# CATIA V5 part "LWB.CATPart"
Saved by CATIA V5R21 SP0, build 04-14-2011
Part number: LWB.SLDPRT
Bounding box of the stored display mesh (mm): x 1.55 to 5.05, y 3.678 to 6.478, z -1.805 to -0.004
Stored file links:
  C:\Users\user\Desktop\CATIA文件\0-最新文件(2025.3月之前的慎用)\LWB\LWB.CATPart
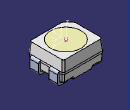
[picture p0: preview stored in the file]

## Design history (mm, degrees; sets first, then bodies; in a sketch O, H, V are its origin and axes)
AxisSystem1: origin (3.2981, 5.075, -0.0046), X (0, -1, 0), Y (1, 0, 0), Z (0, 0, 1)
Set1
  DatumSurface1 to DatumSurface120
  Line1: stored without definition
  Circle1: stored without definition
  Line2: stored without definition
  Circle2: stored without definition
  Line3 to Line38: stored without definition
  Circle3: stored without definition
  Line39: stored without definition
  Circle4: stored without definition
  Line40 to Line43: stored without definition
  Circle5: stored without definition
  Circle6: stored without definition
  Line44 to Line46: stored without definition
  Circle7: stored without definition
  Line47: stored without definition
  Circle8: stored without definition
  Line48 to Line50: stored without definition
  Circle9 to Circle11: stored without definition
  Line51: stored without definition
  Circle12: stored without definition
  Line52: stored without definition
  Circle13 to Circle15: stored without definition
  Line53: stored without definition
  Circle16: stored without definition
  Line54: stored without definition
  Circle17 to Circle19: stored without definition
  Line55: stored without definition
  Circle20: stored without definition
  Line56: stored without definition
  Circle21 to Circle23: stored without definition
  Line57: stored without definition
  Circle24: stored without definition
  Line58: stored without definition
  Circle25: stored without definition
  Circle26: stored without definition
  Line59 to Line62: stored without definition
  Circle27: stored without definition
  Circle28: stored without definition
  Line63 to Line66: stored without definition
  Circle29: stored without definition
  Circle30: stored without definition
  Line67: stored without definition
  Circle31: stored without definition
  Line68: stored without definition
  Circle32: stored without definition
  Line69 to Line72: stored without definition
  Circle33: stored without definition
  Line73: stored without definition
  Circle34: stored without definition
  Circle35: stored without definition
  Line74: stored without definition
  Circle36: stored without definition
  Line75 to Line78: stored without definition
  Circle37: stored without definition
  Line79: stored without definition
  Circle38: stored without definition
  Line80 to Line82: stored without definition
  Circle39: stored without definition
  Line83: stored without definition
  Circle40: stored without definition
  Line84 to Line86: stored without definition
  Circle41: stored without definition
  Line87: stored without definition
  Circle42: stored without definition
  Line88 to Line90: stored without definition
  Circle43: stored without definition
  Line91: stored without definition
  Circle44: stored without definition
  Circle45: stored without definition
  Line92: stored without definition
  Circle46: stored without definition
  Line93 to Line95: stored without definition
  Circle47: stored without definition
  Line96: stored without definition
  Circle48: stored without definition
  Circle49: stored without definition
  Line97: stored without definition
  Circle50: stored without definition
  Line98 to Line100: stored without definition
  Circle51: stored without definition
  Line101: stored without definition
  Circle52: stored without definition
  Line102 to Line104: stored without definition
  Circle53: stored without definition
  Line105: stored without definition
  Circle54: stored without definition
  Line106 to Line108: stored without definition
  Circle55: stored without definition
  Line109: stored without definition
  Circle56: stored without definition
  Line110 to Line112: stored without definition
  Circle57: stored without definition
  Line113: stored without definition
  Circle58: stored without definition
  Line114: stored without definition
  Circle59: stored without definition
  Line115: stored without definition
  Circle60: stored without definition
  Line116 to Line118: stored without definition
  Circle61: stored without definition
  Line119: stored without definition
  Circle62: stored without definition
  Line120 to Line132: stored without definition
  Circle63: stored without definition
  Line133: stored without definition
  Circle64: stored without definition
  Line134 to Line136: stored without definition
  Circle65: stored without definition
  Line137: stored without definition
  Circle66: stored without definition
  Line138: stored without definition
  Circle67: stored without definition
  Line139: stored without definition
  Circle68: stored without definition
  Line140 to Line143: stored without definition
  Circle69: stored without definition
  Circle70: stored without definition
  Line144 to Line153: stored without definition
  Circle71: stored without definition
  Line154: stored without definition
  Circle72: stored without definition
  Line155 to Line157: stored without definition
  Circle73: stored without definition
  Line158: stored without definition
  Circle74: stored without definition
  Line159 to Line161: stored without definition
  Circle75: stored without definition
  Line162: stored without definition
  Circle76: stored without definition
  Line163 to Line165: stored without definition
  Circle77: stored without definition
  Line166: stored without definition
  Circle78: stored without definition
  Line167 to Line169: stored without definition
  Circle79: stored without definition
  Line170: stored without definition
  Circle80: stored without definition
  Line171 to Line173: stored without definition
  Circle81: stored without definition
  Line174: stored without definition
  Circle82: stored without definition
  Line175 to Line177: stored without definition
  Circle83: stored without definition
  Line178: stored without definition
  Circle84: stored without definition
  Line179 to Line181: stored without definition
  Circle85: stored without definition
  Line182: stored without definition
  Circle86: stored without definition
  Line183 to Line185: stored without definition
  Circle87: stored without definition
  Line186: stored without definition
  Circle88: stored without definition
  Line187 to Line189: stored without definition
  Circle89: stored without definition
  Line190: stored without definition
  Circle90: stored without definition
  Line191 to Line193: stored without definition
  Circle91: stored without definition
  Line194: stored without definition
  Circle92: stored without definition
  Line195 to Line197: stored without definition
  Circle93: stored without definition
  Line198: stored without definition
  Circle94: stored without definition
  Line199 to Line201: stored without definition
  Circle95: stored without definition
  Line202: stored without definition
  Circle96: stored without definition
  Line203 to Line205: stored without definition
  Circle97: stored without definition
  Line206: stored without definition
  Circle98: stored without definition
  Line207 to Line209: stored without definition
  Circle99: stored without definition
  Line210: stored without definition
  Circle100: stored without definition
  Line211 to Line213: stored without definition
  Circle101: stored without definition
  Line214: stored without definition
  Circle102: stored without definition
  Line215 to Line217: stored without definition
  Circle103: stored without definition
  Line218: stored without definition
  Circle104: stored without definition
  Line219 to Line221: stored without definition
  Circle105: stored without definition
  Line222: stored without definition
  Circle106: stored without definition
  Line223 to Line225: stored without definition
  Circle107: stored without definition
  Line226: stored without definition
  Circle108: stored without definition
  Line227 to Line229: stored without definition
  Circle109: stored without definition
  Line230: stored without definition
  Circle110: stored without definition
  Line231 to Line241: stored without definition
  DatumSurface121 to DatumSurface179
  Circle111: stored without definition
  Line242: stored without definition
  Circle112: stored without definition
  Line243: stored without definition
  Circle113 to Circle115: stored without definition
  Line244: stored without definition
  Circle116: stored without definition
  Line245 to Line248: stored without definition
  Circle117: stored without definition
  Circle118: stored without definition
  Line249 to Line251: stored without definition
  Circle119: stored without definition
  Line252: stored without definition
  Circle120: stored without definition
  Line253 to Line256: stored without definition
  Circle121: stored without definition
  Circle122: stored without definition
  Line257 to Line261: stored without definition
  Circle123: stored without definition
  Circle124: stored without definition
  Line262 to Line265: stored without definition
  Circle125 to Circle128: stored without definition
  Line266 to Line270: stored without definition
  Circle129: stored without definition
  Circle130: stored without definition
  Line271 to Line274: stored without definition
  Circle131: stored without definition
  Circle132: stored without definition
  Line275 to Line277: stored without definition
  Circle133: stored without definition
  Circle134: stored without definition
  Line278 to Line282: stored without definition
  Circle135: stored without definition
  Circle136: stored without definition
  Line283 to Line286: stored without definition
  Circle137: stored without definition
  Circle138: stored without definition
  Line287 to Line289: stored without definition
  Circle139: stored without definition
  Circle140: stored without definition
  Line290 to Line293: stored without definition
  Circle141: stored without definition
  Circle142: stored without definition
  Line294 to Line298: stored without definition
  Circle143: stored without definition
  Circle144: stored without definition
  Line299 to Line302: stored without definition
  Circle145: stored without definition
  Circle146: stored without definition
  Line303 to Line306: stored without definition
  Circle147: stored without definition
  Circle148: stored without definition
  Line307 to Line310: stored without definition
  Circle149: stored without definition
  Circle150: stored without definition
  Line311: stored without definition
  Circle151: stored without definition
  Line312: stored without definition
  Circle152 to Circle154: stored without definition
  Line313 to Line316: stored without definition
  Circle155: stored without definition
  Circle156: stored without definition
  Line317 to Line320: stored without definition
  Circle157: stored without definition
  Circle158: stored without definition
  Line321: stored without definition
  Line322: stored without definition
  Circle159: stored without definition
  Circle160: stored without definition
  Line323 to Line325: stored without definition
  Circle161: stored without definition
  Circle162: stored without definition
  Line326 to Line330: stored without definition
  Circle163: stored without definition
  Circle164: stored without definition
  Line331 to Line334: stored without definition
  Circle165: stored without definition
  Circle166: stored without definition
  Line335 to Line337: stored without definition
  Circle167: stored without definition
  Circle168: stored without definition
  Line338 to Line342: stored without definition
  Circle169: stored without definition
  Line343 to Line345: stored without definition
  Circle170: stored without definition
  Line346 to Line352: stored without definition
  DatumSurface180 to DatumSurface389
  Circle171: stored without definition
  Circle172: stored without definition
  Line353: stored without definition
  Line354: stored without definition
  Circle173: stored without definition
  Circle174: stored without definition
  DatumCurve1
  Line355: stored without definition
  Line356: stored without definition
  Circle175: stored without definition
  Line357: stored without definition
  DatumCurve2
  Circle176: stored without definition
  Line358: stored without definition
  Circle177 to Circle183: stored without definition
  Line359: stored without definition
  Line360: stored without definition
  Circle184 to Circle188: stored without definition
  Line361: stored without definition
  Circle189: stored without definition
  Line362: stored without definition
  Circle190 to Circle192: stored without definition
  Line363: stored without definition
  Circle193: stored without definition
  Line364: stored without definition
  Circle194 to Circle196: stored without definition
  Line365: stored without definition
  Circle197: stored without definition
  Line366: stored without definition
  Circle198 to Circle200: stored without definition
  Line367: stored without definition
  Circle201: stored without definition
  Line368: stored without definition
  Circle202 to Circle204: stored without definition
  Line369 to Line373: stored without definition
  Circle205: stored without definition
  Line374: stored without definition
  Circle206 to Circle208: stored without definition
  Line375: stored without definition
  Circle209: stored without definition
  Line376: stored without definition
  Circle210: stored without definition
  Line377 to Line379: stored without definition
  Circle211: stored without definition
  Circle212: stored without definition
  Line380 to Line383: stored without definition
  Circle213: stored without definition
  Circle214: stored without definition
  Line384 to Line388: stored without definition
  Circle215: stored without definition
  Circle216: stored without definition
  Line389 to Line391: stored without definition
  Circle217: stored without definition
  Circle218: stored without definition
  Line392: stored without definition
  Line393: stored without definition
  Circle219: stored without definition
  Circle220: stored without definition
  Line394 to Line397: stored without definition
  Circle221: stored without definition
  Circle222: stored without definition
  Line398 to Line401: stored without definition
  Circle223 to Circle226: stored without definition
  Line402 to Line405: stored without definition
  Circle227: stored without definition
  Circle228: stored without definition
  Line406 to Line409: stored without definition
  Circle229: stored without definition
  Circle230: stored without definition
  Line410 to Line413: stored without definition
  Circle231: stored without definition
  Circle232: stored without definition
  Line414 to Line417: stored without definition
  Circle233: stored without definition
  Circle234: stored without definition
  Line418 to Line422: stored without definition
  Circle235: stored without definition
  Circle236: stored without definition
  Line423 to Line426: stored without definition
  Circle237: stored without definition
  Circle238: stored without definition
  Line427 to Line429: stored without definition
  Circle239: stored without definition
  Circle240: stored without definition
  Line430 to Line433: stored without definition
  Circle241: stored without definition
  Circle242: stored without definition
  Line434 to Line438: stored without definition
  Circle243: stored without definition
  Circle244: stored without definition
  Line439 to Line441: stored without definition
  Circle245: stored without definition
  Circle246: stored without definition
  Line442 to Line445: stored without definition
  Circle247: stored without definition
  Circle248: stored without definition
  Line446 to Line450: stored without definition
  Circle249 to Circle252: stored without definition
  Line451 to Line454: stored without definition
  Circle253: stored without definition
  Circle254: stored without definition
  Line455 to Line459: stored without definition
  Circle255 to Circle257: stored without definition
  Line460: stored without definition
  Circle258: stored without definition
  Line461 to Line464: stored without definition
  Circle259: stored without definition
  Line465: stored without definition
  Circle260: stored without definition
  Line466 to Line468: stored without definition
  Circle261: stored without definition
  Line469: stored without definition
  Circle262: stored without definition
  Line470 to Line472: stored without definition
  Circle263: stored without definition
  Line473: stored without definition
  Circle264: stored without definition
  Line474 to Line476: stored without definition
  Circle265: stored without definition
  Line477: stored without definition
  Circle266: stored without definition
  Line478 to Line480: stored without definition
  Circle267: stored without definition
  Line481: stored without definition
  Circle268: stored without definition
  Line482 to Line484: stored without definition
  Circle269: stored without definition
  Line485: stored without definition
  Circle270: stored without definition
  Line486 to Line488: stored without definition
  Circle271: stored without definition
  Line489: stored without definition
  Circle272: stored without definition
  Line490 to Line492: stored without definition
  Circle273: stored without definition
  Line493: stored without definition
  Circle274: stored without definition
  Line494 to Line496: stored without definition
  Circle275: stored without definition
  Line497: stored without definition
  Circle276: stored without definition
  Line498 to Line500: stored without definition
  Circle277: stored without definition
  Line501: stored without definition
  Circle278: stored without definition
  Line502 to Line509: stored without definition
  Circle279: stored without definition
  Circle280: stored without definition
  DatumCurve3
  DatumCurve4
  Circle281: stored without definition
  Line510 to Line512: stored without definition
  DatumCurve5
  Circle282: stored without definition
  Circle283: stored without definition
  DatumCurve6
  DatumCurve7
  Line513: stored without definition
  DatumCurve8
  Line514: stored without definition
  Circle284: stored without definition
  DatumCurve9
  Circle285: stored without definition
  Line515: stored without definition
  Circle286: stored without definition
  Line516: stored without definition
  DatumCurve10
  Circle287: stored without definition
  Circle288: stored without definition
  Line517: stored without definition
  Line518: stored without definition
  DatumCurve11
  Circle289: stored without definition
  DatumCurve12
  Line519: stored without definition
  Circle290: stored without definition
  Line520: stored without definition
  DatumCurve13
  Circle291: stored without definition
  Line521: stored without definition
  Circle292: stored without definition
  Line522: stored without definition
  Line523: stored without definition
  Circle293: stored without definition
  Line524: stored without definition
  DatumCurve14
  Circle294: stored without definition
  Line525: stored without definition
  Line526: stored without definition
  Circle295: stored without definition
  Circle296: stored without definition
  Line527 to Line529: stored without definition
  DatumCurve15
  Line530: stored without definition
  Circle297: stored without definition
  DatumCurve16
  Line531: stored without definition
  Circle298: stored without definition
  Line532: stored without definition
  Line533: stored without definition
  DatumCurve17
  Circle299: stored without definition
  Line534: stored without definition
  Line535: stored without definition
  Circle300: stored without definition
  Circle301: stored without definition
  Line536: stored without definition
  Line537: stored without definition
  Circle302: stored without definition
  Line538: stored without definition
  Circle303: stored without definition
  Line539 to Line542: stored without definition
  DatumCurve18
  Line543: stored without definition
  DatumCurve19
  Circle304: stored without definition
  DatumCurve20
  Line544: stored without definition
  Circle305: stored without definition
  Line545: stored without definition
  DatumCurve21
  DatumCurve22
  Line546: stored without definition
  Circle306 to Circle308: stored without definition
  Line547: stored without definition
  Circle309: stored without definition
  Line548: stored without definition
  Line549: stored without definition
  DatumCurve23
  Line550 to Line555: stored without definition
  Circle310: stored without definition
  Line556: stored without definition
  Circle311: stored without definition
  Line557 to Line559: stored without definition
  Circle312: stored without definition
  Line560: stored without definition
  Circle313: stored without definition
  Line561 to Line580: stored without definition
  Circle314: stored without definition
  Line581: stored without definition
  DatumCurve24
  Line582: stored without definition
  DatumCurve25
  Line583 to Line588: stored without definition
  Circle315: stored without definition
  Line589: stored without definition
  Circle316: stored without definition
  Line590 to Line592: stored without definition
  Circle317: stored without definition
  Line593: stored without definition
  Circle318: stored without definition
  Line594 to Line596: stored without definition
  Circle319: stored without definition
  Line597: stored without definition
  Circle320: stored without definition
  Line598 to Line600: stored without definition
  Circle321: stored without definition
  Line601: stored without definition
  Circle322: stored without definition
  Line602 to Line604: stored without definition
  Circle323: stored without definition
  Line605: stored without definition
  Circle324: stored without definition
  Circle325: stored without definition
  Line606: stored without definition
  Circle326: stored without definition
  Line607 to Line609: stored without definition
  Circle327: stored without definition
  Line610: stored without definition
  Circle328: stored without definition
  Circle329: stored without definition
  Line611: stored without definition
  Circle330: stored without definition
  Line612 to Line614: stored without definition
  Circle331: stored without definition
  Line615: stored without definition
  Circle332: stored without definition
  Line616 to Line618: stored without definition
  Circle333: stored without definition
  Line619: stored without definition
  Circle334: stored without definition
  Line620 to Line622: stored without definition
  Circle335: stored without definition
  Line623: stored without definition
  Circle336: stored without definition
  Line624 to Line626: stored without definition
  Circle337: stored without definition
  Line627: stored without definition
  Circle338: stored without definition
  Line628 to Line634: stored without definition
  Circle339: stored without definition
  DatumCurve26
  Line635: stored without definition
  DatumCurve27
  Line636: stored without definition
  Line637: stored without definition
  DatumCurve28
  Line638: stored without definition
  DatumCurve29
  Circle340: stored without definition
  Line639: stored without definition
  DatumCurve30
  Line640 to Line642: stored without definition
  DatumCurve31
  Line643 to Line645: stored without definition
  DatumCurve32
  Circle341: stored without definition
  Line646 to Line650: stored without definition
  DatumCurve33
  Circle342: stored without definition
  Line651 to Line664: stored without definition
  Circle343: stored without definition
  Line665: stored without definition
  Circle344: stored without definition
  Line666: stored without definition
  Circle345: stored without definition
  Line667: stored without definition
  Circle346: stored without definition
  Line668: stored without definition
  Circle347: stored without definition
  Line669: stored without definition
  Circle348: stored without definition
  Line670: stored without definition
  Circle349: stored without definition
  DatumCurve34
  Line671 to Line674: stored without definition
  Circle350: stored without definition
  Line675 to Line677: stored without definition
  Circle351: stored without definition
  Line678: stored without definition
  Line679: stored without definition
  Circle352: stored without definition
  Line680 to Line683: stored without definition
  Circle353: stored without definition
  Line684: stored without definition
  Line685: stored without definition
  Circle354: stored without definition
  Line686 to Line688: stored without definition
  Circle355: stored without definition
  Line689 to Line692: stored without definition
  Circle356: stored without definition
  Line693 to Line702: stored without definition
  DatumCurve35
  Line703: stored without definition
  DatumCurve36
  Circle357: stored without definition
  Line704: stored without definition
  Line705: stored without definition
  Circle358: stored without definition
  Point1 "发光中心&几何中心（测试原点）": type Center, Curve edge of DatumSurface344
  Point2 "虚拟坐标": (0.0194, 0.0038, -0.0727), relative to Point1, in AxisSystem1
Body1 (main body)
